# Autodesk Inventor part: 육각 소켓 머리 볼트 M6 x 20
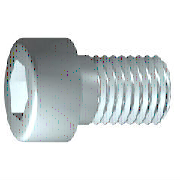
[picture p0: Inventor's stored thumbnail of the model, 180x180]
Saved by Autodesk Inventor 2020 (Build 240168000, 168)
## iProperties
Created: 2012-02
Part Number: 육각 소켓 머리 볼트 M6 x 20
Material: 강철, 연강
Description: 6각 소켓 머리 캡 나사
Document SubType Name: Modeling
Standard: ISO 4762
Designer: mdu-01
Standard Revision: Fourth edition 2004-03-01
Standards Organization: ISO
Language: ko-KR
Size Designation: M6 x 20
Categories: <MemberInstance><Categories><Category DisplayName="조임쇠" InternalName="e4da775c-781d-43d5-af7c-5136215cf5a6" Mnemonic="FSTN"><Category DisplayName="볼트" InternalN
Density: 7.86 g/cm^3
Appearance: 강철
Mass: 7.48273 g
Surface Area: 7.641 cm^2
Volume: 0.952002 cm^3
IsCustomPart: 1
Author: mdu-01
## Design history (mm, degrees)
sketch "스케치1"
  geometry: L1 (-1.333, 0)-(20, 0); L2 (20, 0)-(20, 3); L3 (20, 3)-(2.5, 3); L4 (2.5, 3)-(1.886, 3); L5 (1.886, 3)-(0, 3); L6 (0, 3)-(0, 5); L7 (0, 5)-(-6, 5); L8 (-6, 5)-(-6, 2.887); L9 (-6, 2.887)-(-3, 2.887); L10 (-3, 2.887)-(-1.333, 0); L11 (-11.2, 0)-(25.2, 0) reference; L12 (0, -1)-(0, 6) reference; L13 (2.5, 3)-(0, 3)
  constraints: 22 end point, 6 parallel, 2 collinear, 2 perpendicular, 1 horizontal, 1 point on line
  dimensions: "d1" = 17.5 distance from line of L3.end L2 (= GEL); "d2" = 0.61355 distance of L4.end L3.end (computed from GAL); "d3" = 6 distance between parallel lines of L8 L6 (= KOH); "d4" = 3 distance of L8.end L9.end (= INTI); "d5" = 60 deg angle of L10 L1; "d6" = 6 diameter of L3 L1 (= GD); "d7" = 6 diameter of L5 L1 (= BDM); "d8" = 5.7735 diameter of L9 L1 (= 1.1547 x SW); "d9" = 10 diameter of L7 L1 (= KOD); "d26" = 20 distance between parallel lines of L12 L2 (= NLG)
revolve "본체" sketch "스케치1" stored, may be unused: angle "d10" = 90 deg
sketch "스케치2"
  geometry: L1 (0, -7)-(0, 7) reference; L2 (-7, 0)-(7, 0) reference; L3 (2.887, 0)-(1.443, -2.5); L4 (1.443, -2.5)-(-1.443, -2.5); L5 (-1.443, -2.5)-(-2.887, 0); L6 (-2.887, 0)-(-1.443, 2.5); L7 (-1.443, 2.5)-(1.443, 2.5); L8 (1.443, 2.5)-(2.887, 0); 2 further points
  constraints: 12 end point, 1 coincident, 1 horizontal alignment, 1 point on line, 12 other
extrude "슬롯" join sketch "스케치2" stored distance "d11" = 10; taper "d12" = 0 deg
workplane "Work Plane1"
fillet "Fillet2" dims "d30" = 0.1 (= R)
body "Solid1"
fillet "모깎기1" dims "d17" = 0.6 (= RR)
feature "스레드" dims "d13" = 17.5 (= GEL), "d14" = 0
chamfer "모따기1" distance "d15" = 0.61345 (= -0.5 x SPD + 0.5 x GD); stored, may be unused: second distance "d16" = 0.61345 (= GUL), angle "d27" = 45 deg
other parameters: "GD" = 6 [user parameter; used in 2 equation terms], "NLG" = 20 [user parameter; used in 1 equation term], "GEL" = 17.5 [user parameter; used in 2 equation terms], "KOD" = 10 [user parameter; used in 1 equation term], "KOH" = 6 [user parameter; used in 1 equation term], "INTI" = 3 [user parameter; used in 1 equation term], "GAL" = 0.61345 (= 0.61345 x PTC) [user parameter; used in 1 equation term], "GUL" = 0.61345 (= 0.61345 x PTC) [user parameter; used in 1 equation term], "BDM" = 6 (= NND) [user parameter; used in 1 equation term], "SW" = 5 [user parameter; used in 2 equation terms], "RR" = 0.6 [user parameter; used in 1 equation term], "SPD" = 4.7731 (= NND - 1.2269 x PTC) [user parameter; used in 1 equation term], "d19" = 0, "d28" = 0, "d29" = 0, "R" = 0.1 [user parameter; used in 1 equation term], "TOA" = 30 deg [user parameter], "GD1" = 4.7731 (= THREADDIA - 1.2269 x PTC) [user parameter], "THREADDIA" = 6 [user parameter; used in 1 equation term], "FAWI" = 45 deg [user parameter], "PTC" = 1 [user parameter; used in 5 equation terms], "NND" = 6 [user parameter; used in 2 equation terms], "E0" = 5.775 (= 1.155 x SW) [user parameter]
